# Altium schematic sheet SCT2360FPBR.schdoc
size 127 x 101 mm
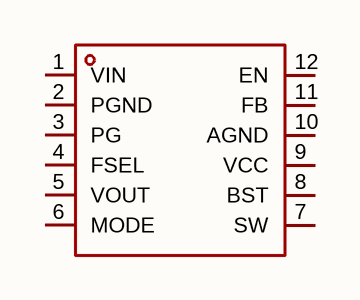
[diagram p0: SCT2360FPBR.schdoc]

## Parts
U?  sct2360fpbr  [QFN-12_L3.0-W3.0-P0.50-TL_SCT2360FPBR]  (value not drawn)

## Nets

Not connected (* = marked no-connect by the designer): U? 1(VIN) 2(PGND) 3(PG) 4(FSEL) 5(VOUT) 6(MODE) 7(SW) 8(BST) 9(VCC) 10(AGND) 11(FB) 12(EN)

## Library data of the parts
U? = sct2360fpbr: 功能类型:降压型;工作电压:4V~28V;输出电压:600mV~14V;输出电流:6A;输出类型:可调;; Manufacturer: SCT(芯洲科技); AddInBom: yes; ModelId: 04312fc7369349919a60b3af93605c89; ModelName: QFN-12_L3.0-W3.0-H0.8-P0.50-TL_SCT2360FPBR; ModelTransform: 118.8974,118.8974,0,0,0,0,-11.81,0.005,0; Function: 降压型; Voltage - Supply: 4V~28V; Output Current: 6A; Frequency - Switching: 400kHz~1.2MHz; Synchronous Rectifier: 是; Number of Outputs: 1; Topology: 降压式; Quiescent Current: 130uA; Switch tube (built-in/external): 内置; Output Type: 可调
